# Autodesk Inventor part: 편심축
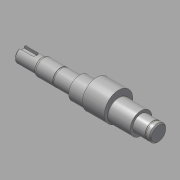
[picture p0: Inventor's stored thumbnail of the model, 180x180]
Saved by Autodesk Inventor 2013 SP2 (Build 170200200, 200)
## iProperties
Created: 2015-12
Part Number: 편심축
Material: 강철, 연강
Document SubType Name: Modeling
Designer: mduedu
Density: 7.86 g/cm^3
Author: mduedu
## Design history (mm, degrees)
sketch "스케치1"
  geometry: L1 (-62.5, 0)-(62.5, 0); L2 (-62.5, 0)-(-62.5, 6.5); L3 (-62.5, 6.5)-(-43.5, 6.5); L4 (-43.5, 7)-(-42.634, 7.5); L5 (-42.634, 7.5)-(-9.5, 7.5); L6 (-9.5, 7.5)-(-9.5, 10); L7 (-9.5, 10)-(46.5, 10); L8 (46.5, 10)-(46.5, 7.5); L9 (46.5, 7.5)-(62.5, 7.5); L10 (62.5, 7.5)-(62.5, 0); L11 (-43.5, 6.5)-(-43.5, 7); 2 further points
  constraints: 22 end point, 6 parallel, 2 perpendicular, 1 coincident, 1 horizontal, 1 midpoint, 1 vertical
  dimensions: "d0" = 13 diameter of L3 L1; "d2" = 15 diameter of L5 L1; "d3" = 20 diameter of L7 L1; "d5" = 15 diameter of L9 L1; "d6" = 125 distance of L1.start L1.end; "d7" = 19 distance of L2.end L3.end; "d8" = 34 distance from line of L6 L3.end; "d9" = 56 distance of L6.end L7.end; "d41" = 14 diameter of L4.start L1; "d42" = 30 deg angle of L4 L3
revolve "회전1" sketch "스케치1" stored, may be unused: angle "d11" = 90 deg
node "작업 평면1"
sketch "스케치2"
  geometry: C1 r 13 at (0, 3); 1 further point
  constraints: 1 centre point, 1 vertical alignment
  dimensions: "d13" = 26 diameter of C1; "d14" = 3 distance of point (0, 0) C1.centre
extrude "돌출1" join sketch "스케치2" distance "d15" = 20; taper "d16" = 0 deg
node "작업 평면2"
sketch "스케치3"
  geometry: L1 (9.5, -2.5)-(-2.5, -2.5); L2 (-2.5, 2.5)-(9.5, 2.5); L3 (9.5, 2.5)-(9.5, -2.5); L4 (9.5, 6.5)-(9.5, -6.5) reference; A1 r 2.5 centre (-2.5, 0) between (-2.5, 2.5) and (-2.5, -2.5); 1 further point
  constraints: 6 end point, 2 point on circle, 2 tangent, 1 centre point, 1 collinear, 1 horizontal, 1 horizontal alignment, 1 parallel
  dimensions: "d17" = 5 distance of L2.end L1.start; "d19" = 12 distance from line of A1.centre L3
extrude "돌출2" cut sketch "스케치3" distance "d20" = 3; taper "d21" = 0 deg
chamfer "모따기1" distance "d22" = 1; stored, may be unused: second distance "d23" = 2, angle "d24" = 45 deg
fillet "모깎기1" dims "d25" = 3
sketch "스케치4"
  geometry: L1 (-9.5, -10)-(-9.5, 10) reference; L2 (-9.5, 0)-(0, 0); L3 (-26.65, 12.15)-(-25.5, 12.15); L4 (-25.5, 12.15)-(-25.5, 7.15); L5 (-25.5, 7.15)-(-26.65, 7.15); L6 (-26.65, 7.15)-(-26.65, 12.15); L7 (57.5, 12.15)-(58.65, 12.15); L8 (58.65, 12.15)-(58.65, 7.15); L9 (58.65, 7.15)-(57.5, 7.15); L10 (57.5, 7.15)-(57.5, 12.15); L11 (62.5, -7.5)-(62.5, 7.5) reference
  constraints: 18 end point, 4 parallel, 2 horizontal, 2 perpendicular, 1 midpoint
  dimensions: "d26" = 16 distance between parallel lines of L4 L1; "d27" = 1.15 distance of L3.start L3.end; "d28" = 14.3 diameter of L5 L2; "d29" = 5 distance of L3.end L4.end; "d30" = 1.15 distance of L7.start L7.end; "d31" = 5 distance of L7.end L8.end; "d32" = 5 distance between parallel lines of L10 L11; "d33" = 14.3 diameter of L9 L2
revolve "회전2" sketch "스케치4" stored, may be unused: angle "d34" = 90 deg
chamfer "모따기2" distance "d35" = 1; stored, may be unused: second distance "d36" = 2, angle "d37" = 45 deg
fillet "모깎기2" dims "d38" = 0.3
sketch "스케치5"
  geometry: 2 further points
  constraints: 1 coincident
sketch "스케치6"
  geometry: 1 further point
hole "구멍1" sketch "스케치6" at (2.5, -3.5) diameter "d43" = 4.917; stored, may be unused: countersink angle "d47" = 90 deg, drill point angle "d49" = 120 deg; dims "d44" = 14, "d45" = 4, "d46" = 2, "d48" = 17
node "솔리드1"
other parameters: "d12" = -15.5
